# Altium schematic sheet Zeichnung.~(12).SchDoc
size A4; PageSetup: Record=PageOptions¦CenterHorizontal=True¦CenterVertical=True¦PrintScale=1.00¦XCorrection=1.00¦YCorrection=1.00¦PrintKind=0¦BorderSize=5000000¦LeftOffset=0¦BottomOffset=0¦Orientation=2¦PaperLength=1000¦PaperWidth=1000¦Scale=100¦PaperSource=7¦PrintQuality=-3¦MediaType=1¦DitherType=10¦PrintScaleMode=1¦PaperKind=A4¦PaperIndex=9
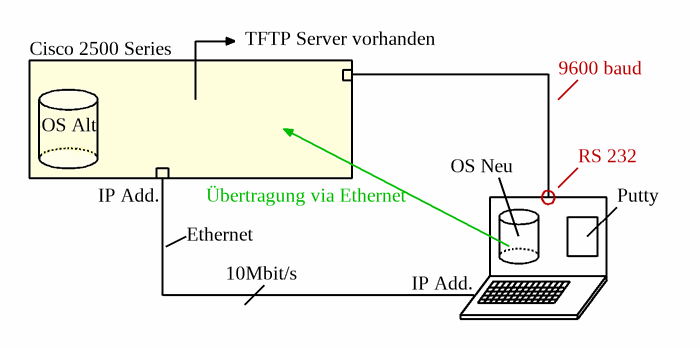
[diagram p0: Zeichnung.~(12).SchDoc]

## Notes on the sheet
- Cisco 2500 Series
- TFTP Server vorhanden
- 9600 baud
- OS Alt
- OS Neu
- RS 232
- IP Add.
- Ethernet
- Übertragung via Ethernet
- Putty
- 10Mbit/s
